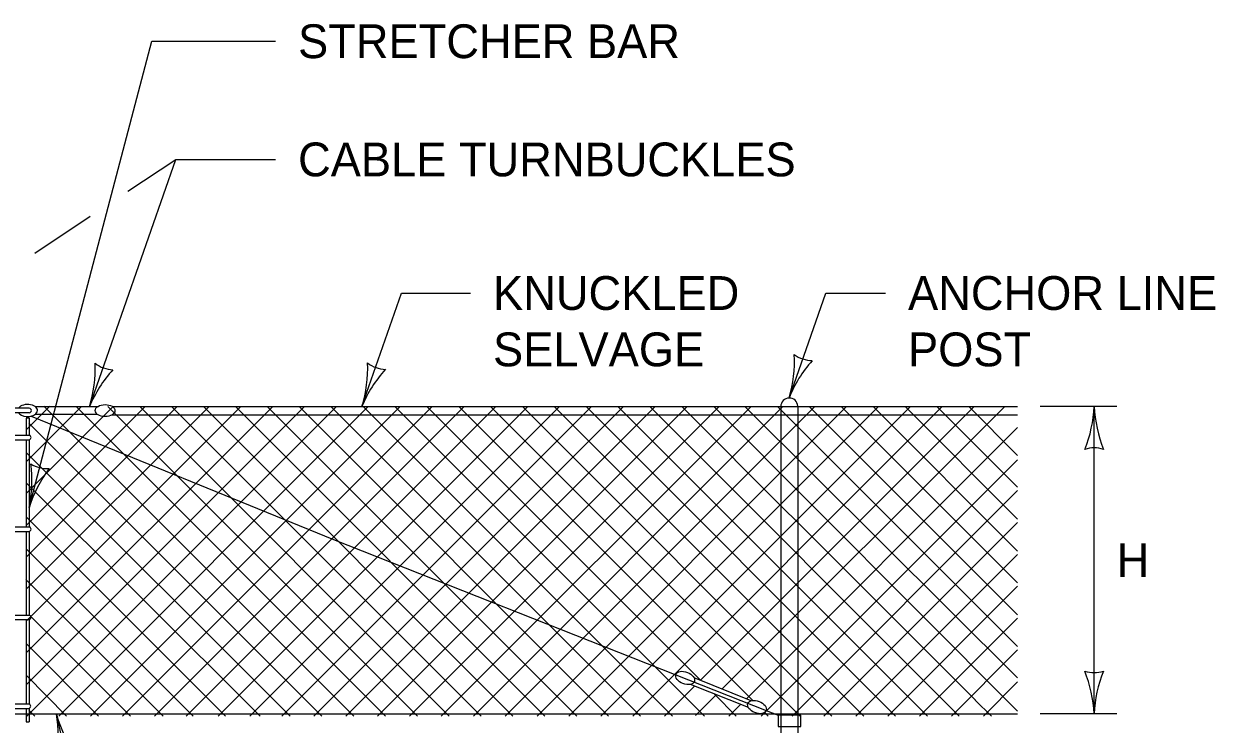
# Model space of a CAD drawing. Extents: x 49973.1 to 50021, y 49987.6 to 50015.4.
# Drawn here: x 49978.561 to 49980.674, y 50009.022 to 50010.264 of the extents above; entities that cross this region are included whole.
import ezdxf

# ---------------------------------------------------------------- set-up
doc = ezdxf.new("R2010")
doc.units = 0
for name, color, linetype in [('Level 1', 7, 'Continuous'), ('Level 2', 7, 'Continuous'), ('Level 3', 7, 'Continuous')]:
    doc.layers.add(name, color=color, linetype=linetype)

msp = doc.modelspace()

# ---------------------------------------------------------------- linework, layer by layer
at = {"layer": 'Level 1'}
for p, q in [((49978.5701, 50009.5825), (49978.4995, 50009.5825)), ((49978.5701, 50009.5744), (49978.4997, 50009.5744)), ((49978.5646, 50009.4872), (49978.6629, 50009.5855)), ((49978.5648, 50009.544), (49978.6071, 50009.5863)), ((49978.5651, 50009.1483), (49979.0023, 50009.5855)), ((49978.5651, 50009.2613), (49978.8893, 50009.5855)), ((49978.5651, 50009.2049), (49978.9457, 50009.5855)), ((49978.5651, 50009.3745), (49978.7761, 50009.5855)), ((49978.5651, 50009.3179), (49978.8327, 50009.5855)), ((49978.5651, 50009.4311), (49978.7195, 50009.5855)), ((49978.5651, 50009.0917), (49979.0589, 50009.5855)), ((49978.5663, 50009.0363), (49979.1155, 50009.5855)), ((49978.5735, 50009.5684), (49979.1099, 50009.3496)), ((49978.6911, 50009.5715), (49978.5807, 50009.5715)), ((49978.6913, 50009.5849), (49978.5817, 50009.5847)), ((49978.596, 50009.5863), (49979.1464, 50009.0363)), ((49978.6227, 50009.0363), (49979.1719, 50009.5855)), ((49978.6534, 50009.5855), (49979.2026, 50009.0363)), ((49978.6793, 50009.0363), (49979.2285, 50009.5855)), ((49978.7099, 50009.5855), (49979.2589, 50009.0363)), ((49978.717, 50009.5705), (49979.8952, 50009.5705)), ((49978.7176, 50009.5855), (49980.3238, 50009.5855)), ((49978.7359, 50009.0363), (49979.2851, 50009.5855)), ((49978.7663, 50009.5855), (49979.3155, 50009.0363)), ((49978.7925, 50009.0363), (49979.3417, 50009.5855)), ((49978.8229, 50009.5855), (49979.3721, 50009.0363)), ((49979.3981, 50009.5855), (49978.8489, 50009.0363)), ((49978.8796, 50009.5855), (49979.4283, 50009.0363)), ((49979.4547, 50009.5855), (49978.9055, 50009.0363)), ((49978.9362, 50009.5855), (49979.4849, 50009.0363)), ((49979.5114, 50009.5855), (49978.9617, 50009.0363)), ((49978.9927, 50009.5855), (49979.5417, 50009.0363)), ((49979.5679, 50009.5855), (49979.0187, 50009.0363)), ((49979.0493, 50009.5855), (49979.598, 50009.0363)), ((49979.6247, 50009.5855), (49979.0755, 50009.0363)), ((49979.1057, 50009.5855), (49979.6547, 50009.0363)), ((49979.6811, 50009.5855), (49979.1319, 50009.0363)), ((49979.1625, 50009.5855), (49979.7117, 50009.0363)), ((49979.7377, 50009.5855), (49979.1882, 50009.0363)), ((49979.219, 50009.5855), (49979.7686, 50009.0363)), ((49979.7942, 50009.5855), (49979.2449, 50009.0363)), ((49979.2757, 50009.5855), (49979.7616, 50009.0996)), ((49979.8509, 50009.5855), (49979.3014, 50009.0363)), ((49979.3323, 50009.5855), (49979.8539, 50009.0639)), ((49979.9075, 50009.5855), (49979.3583, 50009.0363)), ((49979.9379, 50009.0363), (49979.3887, 50009.5855)), ((49979.9641, 50009.5855), (49979.4149, 50009.0363)), ((49979.9945, 50009.0363), (49979.4453, 50009.5855)), ((49980.0205, 50009.5855), (49979.4713, 50009.0363)), ((49980.0511, 50009.0363), (49979.5019, 50009.5855)), ((49980.077, 50009.5855), (49979.5278, 50009.0363)), ((49980.1074, 50009.0363), (49979.5585, 50009.5855)), ((49980.1336, 50009.5855), (49979.5844, 50009.0363)), ((49980.1641, 50009.0363), (49979.6149, 50009.5855)), ((49980.1903, 50009.5855), (49979.6411, 50009.0363)), ((49980.2203, 50009.0363), (49979.6715, 50009.5855)), ((49979.8095, 50009.5041), (49979.7281, 50009.5855)), ((49980.2468, 50009.5855), (49979.7611, 50009.0998)), ((49980.3238, 50009.0449), (49979.7847, 50009.5855)), ((49980.301, 50009.5855), (49979.7998, 50009.0843)), ((49980.3238, 50009.1042), (49979.8399, 50009.5855)), ((49979.8952, 50009.5705), (49980.3238, 50009.5705)), ((49980.3238, 50009.1594), (49979.8977, 50009.5855)), ((49979.9038, 50009.5855), (49979.9038, 50008.5907)), ((49979.9338, 50009.5855), (49979.9338, 50008.5907)), ((49980.3238, 50009.216), (49979.9543, 50009.5855)), ((49980.3238, 50009.2726), (49980.0109, 50009.5855)), ((49980.3238, 50009.3291), (49980.0675, 50009.5855)), ((49980.3238, 50009.3857), (49980.1241, 50009.5855)), ((49980.3238, 50009.4423), (49980.1807, 50009.5855)), ((49980.3238, 50009.4987), (49980.2371, 50009.5855)), ((49978.5651, 50009.5648), (49978.5651, 50009.5345)), ((49978.5701, 50009.5648), (49978.5651, 50009.5648)), ((49978.5699, 50009.5557), (49979.0893, 50009.0363)), ((49978.5701, 50009.5648), (49978.5701, 50009.5345)), ((49980.3238, 50009.5482), (49979.8428, 50009.0669)), ((49978.5144, 50009.5346), (49978.5706, 50009.5346)), ((49978.5144, 50009.5265), (49978.5704, 50009.5265)), ((49978.5651, 50009.5265), (49978.5651, 50009.372)), ((49978.5701, 50009.5265), (49978.5701, 50009.372)), ((49978.5657, 50009.5034), (49979.0331, 50009.0363)), ((49979.8229, 50009.4906), (49979.8095, 50009.5041)), ((49980.0184, 50009.295), (49979.8223, 50009.4911)), ((49980.3238, 50009.4909), (49979.8692, 50009.0363)), ((49978.5655, 50009.4494), (49978.9798, 50009.0363)), ((49980.3238, 50009.4364), (49979.9237, 50009.0363)), ((49978.5651, 50009.39), (49978.9183, 50009.0363)), ((49980.3238, 50009.3798), (49979.9803, 50009.0363)), ((49978.5144, 50009.3718), (49978.5706, 50009.3718)), ((49978.5144, 50009.3637), (49978.5704, 50009.3637)), ((49978.5651, 50009.3639), (49978.5651, 50009.2154)), ((49978.5701, 50009.3638), (49978.5701, 50009.2155)), ((49979.1102, 50009.3495), (49979.7176, 50009.1094)), ((49978.5649, 50009.3327), (49978.861, 50009.0363)), ((49980.3238, 50009.3232), (49980.0369, 50009.0363)), ((49980.2491, 50009.0643), (49980.0175, 50009.296)), ((49978.5645, 50009.2785), (49978.8077, 50009.0363)), ((49980.3238, 50009.2666), (49980.0935, 50009.0363)), ((49978.5142, 50009.2154), (49978.5704, 50009.2154)), ((49978.5744, 50009.212), (49978.7499, 50009.0363)), ((49980.3238, 50009.21), (49980.1501, 50009.0363)), ((49978.5142, 50009.2073), (49978.5702, 50009.2073)), ((49978.5651, 50009.2073), (49978.5651, 50009.0578)), ((49978.5701, 50009.2073), (49978.5701, 50009.0577)), ((49978.5653, 50009.1645), (49978.6932, 50009.0363)), ((49980.3238, 50009.1536), (49980.2065, 50009.0363)), ((49980.0877, 50009.1437), (49980.0864, 50009.1424)), ((49978.5652, 50009.1081), (49978.6365, 50009.0363)), ((49979.7176, 50009.1094), (49979.8778, 50009.046)), ((49979.8514, 50009.0635), (49979.7502, 50009.1042)), ((49979.7504, 50009.0891), (49979.6975, 50009.0363)), ((49979.8462, 50009.0512), (49979.7438, 50009.0924)), ((49980.3238, 50009.097), (49980.2631, 50009.0363)), ((49979.7891, 50009.0738), (49979.7525, 50009.0372)), ((49979.8247, 50009.0363), (49979.786, 50009.0751)), ((49980.2773, 50009.0363), (49980.2488, 50009.0647)), ((49978.4511, 50009.04), (49980.3238, 50009.04)), ((49978.5138, 50009.0578), (49978.57, 50009.0578)), ((49978.5138, 50009.0497), (49978.5698, 50009.0497)), ((49978.5651, 50009.0497), (49978.5651, 50009.0258)), ((49978.5699, 50009.0467), (49978.5803, 50009.0363)), ((49978.5701, 50009.0497), (49978.5701, 50009.0259)), ((49979.8321, 50009.0567), (49979.8117, 50009.0363)), ((49979.8783, 50009.0455), (49979.8691, 50009.0363)), ((49979.8813, 50009.0363), (49979.8753, 50009.0423)), ((49979.8778, 50009.046), (49979.8989, 50009.0377)), ((49978.5651, 50009.0258), (49978.5701, 50009.0259))]:
    msp.add_line(p, q, dxfattribs=at)
msp.add_lwpolyline([(49979.8989, 50009.0377), (49979.8989, 50009.0179), (49979.939, 50009.0179), (49979.939, 50009.0377)], close=True, dxfattribs=at)
for centre, radius, start, end in [((49979.9188, 50009.5855), 0.015, 2.6745, 180.7625), ((49978.5701, 50009.5784), 0.00405, 269.3348, 90.4595), ((49978.5693, 50009.5307), 0.00417, 282.5816, 72.0167), ((49978.5693, 50009.3679), 0.00417, 282.5816, 72.0167), ((49978.5691, 50009.2115), 0.00417, 282.5816, 72.0167), ((49978.5687, 50009.0539), 0.00417, 282.5816, 72.0167)]:
    msp.add_arc(centre, radius, start, end, dxfattribs=at)
for start_param, end_param in [(4.569027, 9.026485), (3.521347, 4.569027)]:
    msp.add_ellipse((49978.5675, 50009.5784), major_axis=(0.0175, 0.0001), ratio=0.610393, start_param=start_param, end_param=end_param, dxfattribs=at)
for centre, major_axis in [((49978.7049, 50009.5782), (0.0175, 0.0001)), ((49979.7341, 50009.1038), (0.0163, -0.0064)), ((49979.8615, 50009.0523), (0.0163, -0.0064))]:
    msp.add_ellipse(centre, major_axis=major_axis, ratio=0.610393, dxfattribs=at)
at = {"layer": 'Level 3'}
for p, q in [((49978.5701, 50009.406), (49978.7879, 50010.2335)), ((49978.7879, 50010.2335), (49979.0073, 50010.2335)), ((49978.6772, 50009.5848), (49978.8305, 50010.0238)), ((49978.7453, 50009.9673), (49978.8305, 50010.0238)), ((49978.8305, 50010.0238), (49979.0073, 50010.0238)), ((49978.58, 50009.8576), (49978.6787, 50009.9231)), ((49979.1607, 50009.5855), (49979.231, 50009.7868)), ((49979.231, 50009.7868), (49979.3532, 50009.7868)), ((49979.9184, 50009.6005), (49979.9835, 50009.7868)), ((49979.9835, 50009.7868), (49980.0895, 50009.7868)), ((49980.4997, 50009.5855), (49980.3638, 50009.5855)), ((49980.4597, 50009.04), (49980.4597, 50009.5855)), ((49978.6184, 50009.04), (49978.6578, 50008.8646)), ((49980.5, 50009.04), (49980.3638, 50009.04))]:
    msp.add_line(p, q, dxfattribs=at)
for centre, radius, start, end in [((49979.6949, 50009.6665), 0.233, 343.566, 2.8159), ((49979.9607, 50009.7216), 0.0548, 232.8775, 268.5999), ((49978.4544, 50009.653), 0.233, 342.9989, 2.2487), ((49978.7207, 50009.7055), 0.0548, 232.3104, 268.0327), ((49978.9379, 50009.6537), 0.233, 342.9989, 2.2487), ((49979.3665, 50009.5016), 0.2223, 137.6276, 157.8111), ((49979.2042, 50009.7061), 0.0548, 232.3104, 268.0327), ((49980.1251, 50009.5186), 0.2223, 138.1947, 158.3782), ((49978.883, 50009.5009), 0.2223, 137.6276, 157.8111), ((49980.2376, 50009.5947), 0.2223, 337.456, 357.6395), ((49980.6924, 50009.597), 0.233, 182.8273, 202.0772), ((49980.4597, 50009.4573), 0.0548, 72.1388, 107.8612), ((49978.3421, 50009.4538), 0.233, 348.1649, 7.4147), ((49978.6025, 50009.53), 0.0548, 237.4764, 273.1988), ((49978.7827, 50009.3409), 0.2223, 142.7936, 162.9771), ((49980.4597, 50009.1682), 0.0548, 252.1388, 287.8612), ((49980.227, 50009.0285), 0.233, 2.8273, 22.0772), ((49980.6818, 50009.0309), 0.2223, 157.456, 177.6395), ((49978.3997, 50009.0003), 0.2223, 350.101, 10.2845), ((49978.843, 50009.1022), 0.233, 195.4723, 214.7222)]:
    msp.add_arc(centre, radius, start, end, dxfattribs=at)

# ---------------------------------------------------------------- texts
at = {"layer": 'Level 2'}
for s, p in [('STRETCHER BAR', (49979.0473, 50010.2035)), ('CABLE TURNBUCKLES', (49979.0473, 50009.9938)), ('KNUCKLED', (49979.3932, 50009.7568)), ('ANCHOR LINE', (49980.1295, 50009.7568)), ('SELVAGE', (49979.3932, 50009.6568)), ('POST', (49980.1295, 50009.6568)), ('H', (49980.4997, 50009.2828))]:
    msp.add_text(s, height=0.06, dxfattribs=at).set_placement(p)

doc.saveas('drawing.dxf')
